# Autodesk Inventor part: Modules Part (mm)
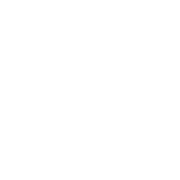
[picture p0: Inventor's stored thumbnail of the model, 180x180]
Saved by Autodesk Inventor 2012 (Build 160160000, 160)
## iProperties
Created: 2008-05
Part Number: Modules Part (mm)
Document SubType Name: Modeling
Designer: Wally
Density: 1 g/cm^3
Material: Default
Author: Wally
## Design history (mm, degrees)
node "Sketch1"
